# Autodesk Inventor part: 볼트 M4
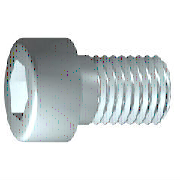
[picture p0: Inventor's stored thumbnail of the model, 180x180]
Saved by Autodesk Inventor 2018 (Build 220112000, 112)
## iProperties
IsCustomPart: 0
Created: 2012-02
Part Number: 볼트 M4
Material: 스테인리스강
Description: 6각 소켓 머리 캡 나사
Document SubType Name: Modeling
Standard: ISO 4762
Designer: mduedu
Standard Revision: Fourth edition 2004-03-01
Standards Organization: ISO
Language: ko-KR
Size Designation: M4 x 10
Categories: <MemberInstance><Categories><Category DisplayName="조임쇠" InternalName="e4da775c-781d-43d5-af7c-5136215cf5a6" Mnemonic="FSTN"><Category DisplayName="볼트" InternalN
Density: 8.08 g/cm^3
Appearance: 반광택
Author: mduedu
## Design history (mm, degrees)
sketch "스케치1"
  geometry: L1 (-1, 0)-(10, 0); L2 (10, 0)-(10, 2); L3 (10, 2)-(1.75, 2); L4 (1.75, 2)-(1.32, 2); L5 (1.32, 2)-(0, 2); L6 (0, 2)-(0, 3.5); L7 (0, 3.5)-(-4, 3.5); L8 (-4, 3.5)-(-4, 1.732); L9 (-4, 1.732)-(-2, 1.732); L10 (-2, 1.732)-(-1, 0); L11 (-6.8, 0)-(12.8, 0) reference; L12 (0, -0.7)-(0, 4.2) reference; L13 (1.75, 2)-(0, 2)
  constraints: 22 end point, 6 parallel, 2 collinear, 2 perpendicular, 1 horizontal, 1 point on line
  dimensions: "d1" = 8.25 distance from line of L3.end L2 (= GEL); "d2" = 0.42952 distance of L4.end L3.end (computed from GAL); "d3" = 4 distance between parallel lines of L8 L6 (= KOH); "d4" = 2 distance of L8.end L9.end (= INTI); "d5" = 60 deg angle of L10 L1; "d6" = 4 diameter of L3 L1 (= GD); "d7" = 4 diameter of L5 L1 (= BDM); "d8" = 3.4641 diameter of L9 L1 (= 1.1547 x SW); "d9" = 7 diameter of L7 L1 (= KOD); "d26" = 10 distance between parallel lines of L12 L2 (= NLG)
revolve "본체" sketch "스케치1" stored, may be unused: angle "d10" = 90 deg
sketch "스케치2"
  geometry: L1 (0, -4.9)-(0, 4.9) reference; L2 (-4.9, 0)-(4.9, 0) reference; L3 (1.732, 0)-(0.866, -1.5); L4 (0.866, -1.5)-(-0.866, -1.5); L5 (-0.866, -1.5)-(-1.732, 0); L6 (-1.732, 0)-(-0.866, 1.5); L7 (-0.866, 1.5)-(0.866, 1.5); L8 (0.866, 1.5)-(1.732, 0); 2 further points
  constraints: 12 end point, 1 coincident, 1 horizontal alignment, 1 point on line, 12 other
extrude "슬롯" join sketch "스케치2" stored distance "d11" = 10; taper "d12" = 0 deg
workplane "Work Plane1"
fillet "Fillet2" dims "d30" = 0.1 (= R)
body "Solid1"
fillet "모깎기1" dims "d17" = 0.4 (= RR)
feature "스레드" dims "d13" = 8.25 (= GEL), "d14" = 0
chamfer "모따기1" distance "d15" = 0.42941 (= -0.5 x SPD + 0.5 x GD); stored, may be unused: second distance "d16" = 0.42941 (= GUL), angle "d27" = 45 deg
other parameters: "GD" = 4 [user parameter; used in 2 equation terms], "NLG" = 10 [user parameter; used in 1 equation term], "GEL" = 8.25 [user parameter; used in 2 equation terms], "KOD" = 7 [user parameter; used in 1 equation term], "KOH" = 4 [user parameter; used in 1 equation term], "INTI" = 2 [user parameter; used in 1 equation term], "GAL" = 0.42941 (= 0.61345 x PTC) [user parameter; used in 1 equation term], "GUL" = 0.42941 (= 0.61345 x PTC) [user parameter; used in 1 equation term], "BDM" = 4 (= NND) [user parameter; used in 1 equation term], "SW" = 3 [user parameter; used in 2 equation terms], "RR" = 0.4 [user parameter; used in 1 equation term], "SPD" = 3.14117 (= NND - 1.2269 x PTC) [user parameter; used in 1 equation term], "d19" = 0, "d28" = 0, "d29" = 0, "R" = 0.1 [user parameter; used in 1 equation term], "TOA" = 30 deg [user parameter], "GD1" = 3.14117 (= THREADDIA - 1.2269 x PTC) [user parameter], "THREADDIA" = 4 [user parameter; used in 1 equation term], "FAWI" = 45 deg [user parameter], "TPU" = 14.28571 (computed from PTC) [user parameter], "PTC" = 0.7 [user parameter; used in 5 equation terms], "NND" = 4 [user parameter; used in 2 equation terms], "E0" = 3.465 (= 1.155 x SW) [user parameter]
